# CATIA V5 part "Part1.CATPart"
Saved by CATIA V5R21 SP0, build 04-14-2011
Part number: Part1
Bounding box of the stored display mesh (mm): x 0 to 20, y -150 to 150, z -40 to 40
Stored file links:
  D:\CATIA V5R21 E-RESOURCES\CATIA-V5R21\catia-v5r21-Prts\c16_catia_v5r21_prt\Slide Curve Joint-(Fig16-40)\Part1.CATPart
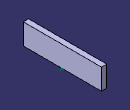
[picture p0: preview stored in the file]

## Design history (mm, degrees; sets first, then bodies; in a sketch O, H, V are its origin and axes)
Body1 (main body)
  Sketch1 on yz-plane, origin (0, 0, 0), H (0, 1, 0), V (0, 0, 1)
    line L1 (150, 40) -> (150, -40)
    line L2 (150, -40) -> (-150, -40)
    line L3 (-150, -40) -> (-150, 40)
    line L4 (-150, 40) -> (150, 40)
    length L4 = 300
    length L1 = 80
    vertical: L1 V, L3 V
    horizontal: L2 H, L4 H
    equidistance: L1 L3 O, L2 L4 O
  Pad1: profile Sketch1, direction (1, 0, 0), length 20
  Point1: type OnCurve, Support edge [face of Pad1 from Sketch1.L2 | end face of Pad1], Ratio 0.5
  Sketch2 on zx-plane, origin (0, 0, 0), H (-1, 0, 0), V (0, 0, 1)
    line L1 (-75, -185) -> (75, -185)
    point P1 (-75, -185)
    distance L1 H = 185
    length L1 = 150
    distance V P1 = 75
    horizontal: L1 H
